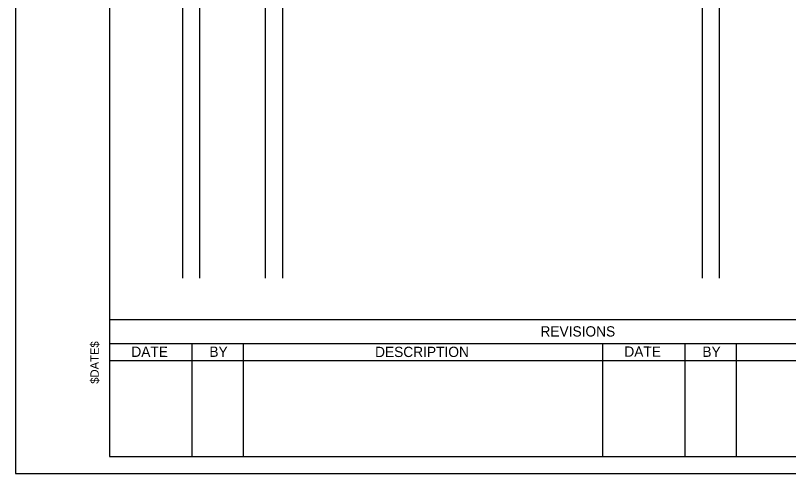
# Model space of a CAD drawing. Extents: x 17890587 to 17890754, y 17897693 to 17897992.
# Drawn here: x 17890586.76 to 17890600.01, y 17897873.1 to 17897880.95 of the extents above; entities that cross this region are included whole.
import ezdxf

# ---------------------------------------------------------------- set-up
doc = ezdxf.new("R2010")
doc.units = 0
for name, color, linetype in [('GSColorFill', 7, 'Continuous'), ('PlotBorder_dp', 7, 'Continuous'), ('SheetBorder_dp', 7, 'Continuous'), ('SheetLines_dp', 7, 'Continuous'), ('TextMinor', 7, 'Continuous'), ('TextMisc', 7, 'Continuous')]:
    doc.layers.add(name, color=color, linetype=linetype)

msp = doc.modelspace()

# ---------------------------------------------------------------- linework, layer by layer
at = {"layer": 'GSColorFill'}
for p, q in [((17890589.617, 17897882.672), (17890589.617, 17897876.45)), ((17890591.332, 17897882.706), (17890591.332, 17897876.45)), ((17890589.911, 17897882.467), (17890589.911, 17897876.45)), ((17890591.038, 17897882.486), (17890591.038, 17897876.45)), ((17890598.526, 17897881.897), (17890598.526, 17897876.45)), ((17890598.82, 17897881.904), (17890598.82, 17897876.45))]:
    msp.add_line(p, q, dxfattribs=at)
at = {"layer": 'PlotBorder_dp'}
msp.add_lwpolyline([(17890586.756, 17897873.104), (17890635.165, 17897873.104), (17890635.165, 17897904.203), (17890586.756, 17897904.203)], close=True, dxfattribs=at)
at = {"layer": 'SheetBorder_dp'}
for p, q in [((17890588.37, 17897903.909), (17890588.37, 17897873.397)), ((17890588.37, 17897875.744), (17890633.551, 17897875.744)), ((17890588.37, 17897873.397), (17890633.551, 17897873.397))]:
    msp.add_line(p, q, dxfattribs=at)
at = {"layer": 'SheetLines_dp'}
for p, q in [((17890588.37, 17897875.334), (17890605.269, 17897875.334)), ((17890589.778, 17897875.334), (17890589.778, 17897873.397)), ((17890590.658, 17897875.334), (17890590.658, 17897873.397)), ((17890596.819, 17897875.334), (17890596.819, 17897873.397)), ((17890598.228, 17897875.334), (17890598.228, 17897873.397)), ((17890599.108, 17897875.334), (17890599.108, 17897873.397)), ((17890588.37, 17897875.04), (17890605.269, 17897875.04))]:
    msp.add_line(p, q, dxfattribs=at)

# ---------------------------------------------------------------- texts
at = {"layer": 'TextMinor'}
msp.add_text('$DATE$', height=0.1438, rotation=90, dxfattribs=at).set_placement((17890588.185, 17897874.642))
at = {"layer": 'TextMisc'}
for s, p in [('REVISIONS', (17890595.754, 17897875.451)), ('BY', (17890590.08, 17897875.102)), ('BY', (17890598.53, 17897875.102))]:
    msp.add_text(s, height=0.176, dxfattribs=at).set_placement(p)
for s, rotation, p in [('DATE', 359.8693, (17890588.742, 17897875.102)), ('DESCRIPTION', 0.0498, (17890592.92, 17897875.099)), ('DATE', 359.8693, (17890597.192, 17897875.105))]:
    msp.add_text(s, height=0.176, rotation=rotation, dxfattribs=at).set_placement(p)

doc.saveas('drawing.dxf')
